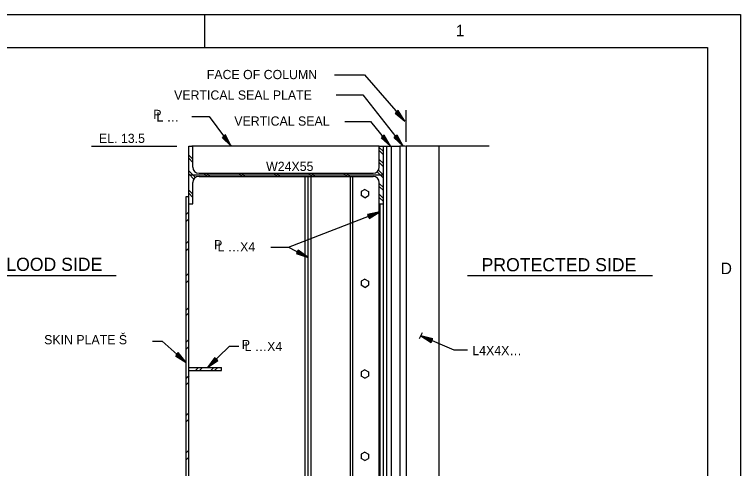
# Model space of a CAD drawing. Extents: x 4.9 to 31.6, y 3.9 to 22.6.
# Drawn here: x 24.23 to 31.57, y 18 to 22.59 of the extents above; entities that cross this region are included whole.
import ezdxf

# ---------------------------------------------------------------- set-up
doc = ezdxf.new("R2010")
doc.units = 0
for name, color, linetype in [('Level 1', 7, 'Continuous'), ('Level 10', 7, 'Continuous'), ('Level 2', 7, 'Continuous'), ('Level 25', 7, 'Continuous'), ('Level 3', 7, 'Continuous'), ('Level 44', 7, 'Continuous'), ('Level 50', 7, 'Continuous')]:
    doc.layers.add(name, color=color, linetype=linetype)

msp = doc.modelspace()

# ---------------------------------------------------------------- linework, layer by layer
at = {"layer": 'Level 1'}
msp.add_line((26.1569, 22.2594), (26.1569, 22.5927), dxfattribs=at)
for points in [[(4.9069, 22.5927), (31.5735, 22.5927), (31.5735, 3.926), (4.9069, 3.926)], [(5.9069, 22.2594), (31.2402, 22.2594), (31.2402, 4.2594), (5.9069, 4.2594)]]:
    msp.add_lwpolyline(points, close=True, dxfattribs=at)
at = {"layer": 'Level 10'}
for p, q in [((26.0618, 18.9926), (26.093, 19.0238)), ((26.1012, 18.9926), (26.1325, 19.0238)), ((26.2154, 18.9926), (26.2467, 19.0238)), ((26.2549, 18.9926), (26.2862, 19.0238))]:
    msp.add_line(p, q, dxfattribs=at)
at = {"layer": 'Level 2'}
for p, q in [((25.9927, 20.6801), (25.9927, 21.2634)), ((25.9927, 21.2634), (26.0343, 21.2634)), ((27.9197, 21.2634), (26.0239, 21.2634)), ((26.0343, 21.0499), (26.0343, 21.2634)), ((26.4504, 21.2634), (26.0773, 21.2634)), ((27.9197, 21.0499), (27.9197, 21.2634)), ((27.9197, 21.2634), (27.9614, 21.2634)), ((27.9614, 21.2634), (28.1281, 21.2634)), ((27.9614, 20.6801), (27.9614, 21.2634)), ((27.9927, 21.2634), (27.9927, 16.5655)), ((28.0395, 21.2634), (28.0395, 15.6699)), ((28.1854, 21.2634), (28.1281, 21.2634)), ((29.0327, 21.2634), (28.1906, 21.2634)), ((25.9927, 20.9717), (27.9614, 20.9717)), ((26.0968, 20.9874), (27.8572, 20.9874)), ((26.0968, 20.9561), (27.8572, 20.9561)), ((27.1697, 17.5238), (27.1697, 20.9561)), ((27.201, 17.5238), (27.201, 20.9561)), ((27.2319, 15.7584), (27.2319, 20.9561)), ((27.6281, 17.1475), (27.6281, 20.9561)), ((26.0343, 20.6801), (26.0343, 20.8936)), ((27.9197, 20.6801), (27.9197, 20.8936)), ((27.7742, 20.8244), (27.7378, 20.8034)), ((27.7378, 20.8034), (27.7378, 20.7616)), ((27.7742, 20.8244), (27.8105, 20.8034)), ((27.8105, 20.8034), (27.8105, 20.7616)), ((25.9666, 20.753), (25.9927, 20.753)), ((25.9666, 17.0688), (25.9666, 20.753)), ((27.7742, 20.7406), (27.7378, 20.7616)), ((27.7742, 20.7406), (27.8105, 20.7616)), ((25.9927, 20.6801), (26.0343, 20.6801)), ((25.9927, 17.0688), (25.9927, 20.6801)), ((27.9197, 20.6801), (27.9614, 20.6801)), ((27.9197, 15.781), (27.9197, 20.6801)), ((27.9302, 17.5238), (27.9302, 20.6801)), ((27.9614, 17.5238), (27.9614, 20.6801)), ((27.7746, 19.9181), (27.7382, 19.8971)), ((27.7746, 19.9181), (27.8109, 19.8971)), ((27.7382, 19.8971), (27.7382, 19.8553)), ((27.7746, 19.8343), (27.7382, 19.8553)), ((27.7746, 19.8343), (27.8109, 19.8553)), ((27.8109, 19.8971), (27.8109, 19.8553)), ((25.9927, 18.9926), (25.9927, 19.0238)), ((26.326, 18.9926), (26.326, 19.0238)), ((27.7746, 19.0014), (27.7382, 18.9804)), ((27.7382, 18.9804), (27.7382, 18.9386)), ((27.7746, 19.0014), (27.8109, 18.9804)), ((27.8109, 18.9804), (27.8109, 18.9386)), ((27.7746, 18.9176), (27.7382, 18.9386)), ((27.7746, 18.9176), (27.8109, 18.9386)), ((27.7746, 18.1685), (27.7382, 18.1475)), ((27.7382, 18.1475), (27.7382, 18.1057)), ((27.7746, 18.1685), (27.8109, 18.1475)), ((27.8109, 18.1475), (27.8109, 18.1057)), ((27.7746, 18.0847), (27.7382, 18.1057)), ((27.7746, 18.0847), (27.8109, 18.1057))]:
    msp.add_line(p, q, dxfattribs=at)
at = {"layer": 'Level 25'}
for p, q in [((28.1906, 21.3056), (28.1906, 21.626)), ((27.9614, 21.2069), (27.9197, 21.2485)), ((26.0343, 21.1295), (25.9927, 21.1712)), ((27.9614, 21.1755), (27.9197, 21.2172)), ((26.0343, 21.0982), (25.9927, 21.1398)), ((27.9614, 21.0852), (27.9197, 21.1268)), ((27.9614, 21.0538), (27.9197, 21.0955)), ((26.0616, 20.9452), (25.9927, 21.0142)), ((27.9614, 20.9389), (27.8988, 21.0014)), ((27.9614, 20.9702), (27.9154, 21.0162)), ((26.0458, 20.9297), (25.9927, 20.9828)), ((26.1764, 20.9561), (26.1451, 20.9874)), ((26.2078, 20.9561), (26.1765, 20.9874)), ((26.5299, 20.9561), (26.4987, 20.9874)), ((26.5613, 20.9561), (26.5301, 20.9874)), ((26.8835, 20.9561), (26.8522, 20.9874)), ((26.9149, 20.9561), (26.8836, 20.9874)), ((27.237, 20.9561), (27.2058, 20.9874)), ((27.2684, 20.9561), (27.2372, 20.9874)), ((27.5906, 20.9561), (27.5594, 20.9874)), ((27.622, 20.9561), (27.5907, 20.9874)), ((27.9614, 20.8438), (27.9197, 20.8854)), ((27.9614, 20.8124), (27.9197, 20.854)), ((26.0343, 20.776), (25.9927, 20.8176)), ((26.0343, 20.7446), (25.9927, 20.7863)), ((27.9614, 20.7338), (27.9197, 20.7755)), ((27.9614, 20.7025), (27.9197, 20.7441)), ((25.2586, 19.952), (23.9288, 19.952)), ((30.6836, 19.952), (28.8131, 19.952)), ((28.3545, 19.375), (28.3242, 19.3143))]:
    msp.add_line(p, q, dxfattribs=at)
for centre, start, end in [((26.0968, 21.0499), 180, 270), ((27.8572, 21.0499), 270, 0), ((26.0968, 20.8936), 90, 180), ((27.8572, 20.8936), 0, 90)]:
    msp.add_arc(centre, 0.0625, start, end, dxfattribs=at)
at = {"layer": 'Level 3'}
for p, q in [((28.156, 21.5419), (28.156, 21.5419)), ((28.1788, 21.5158), (28.1788, 21.5158))]:
    msp.add_line(p, q, dxfattribs=at)
for points in [[(27.4657, 21.9831), (27.7713, 21.9831), (28.1788, 21.5158)], [(27.4852, 21.7803), (27.7533, 21.7803), (28.1612, 21.2634)], [(28.0813, 21.5961), (28.1788, 21.5158), (28.1125, 21.6233), (28.0858, 21.6001), (28.156, 21.5419), (28.111, 21.6149), (28.0939, 21.6), (28.1341, 21.567), (28.1094, 21.6065), (28.1024, 21.6004), (28.1114, 21.5931)], [(27.5707, 21.513), (27.8314, 21.513), (28.0328, 21.2634)], [(28.6776, 19.1997), (28.3397, 19.3454)], [(25.6265, 19.2923), (25.7251, 19.2923), (25.9666, 19.0763)], [(26.4983, 19.2362), (26.4029, 19.2362), (26.1816, 19.0238)]]:
    msp.add_lwpolyline(points, dxfattribs=at)
at = {"layer": 'Level 44'}
for p, q in [((26.0257, 21.5613), (26.2011, 21.5613)), ((26.2011, 21.5613), (26.4235, 21.2634)), ((25.9666, 20.5726), (25.9927, 20.5986)), ((27.0013, 20.2402), (27.9252, 20.5965)), ((25.9666, 20.5007), (25.9927, 20.5268)), ((25.9666, 20.2779), (25.9927, 20.304)), ((25.9666, 20.2061), (25.9927, 20.2321)), ((26.8222, 20.2402), (27.0013, 20.2402)), ((27.0013, 20.2402), (27.201, 20.1364)), ((25.9666, 19.9511), (25.9927, 19.9771)), ((25.9666, 19.88), (25.9927, 19.9061)), ((25.9666, 19.6041), (25.9927, 19.6302)), ((25.9666, 19.5498), (25.9927, 19.5758)), ((25.9666, 19.2823), (25.9927, 19.3083)), ((25.9666, 19.2112), (25.9927, 19.2373)), ((25.9927, 19.0238), (26.326, 19.0238)), ((25.9708, 18.9186), (25.9968, 18.9446)), ((25.9927, 18.9926), (26.326, 18.9926)), ((25.9666, 18.8506), (25.9927, 18.8767)), ((25.9666, 18.5418), (25.9927, 18.5679)), ((25.9666, 18.476), (25.9927, 18.5021)), ((25.9666, 18.1625), (25.9927, 18.1885)), ((25.9666, 18.0906), (25.9927, 18.1167))]:
    msp.add_line(p, q, dxfattribs=at)
at = {"layer": 'Level 50'}
for p, q in [((25.0086, 21.2634), (25.8723, 21.2634)), ((26.4027, 21.2912), (26.4027, 21.2912)), ((26.4235, 21.2634), (26.4235, 21.2634)), ((28.011, 21.2904), (28.011, 21.2904)), ((28.0328, 21.2634), (28.0328, 21.2634)), ((28.1281, 21.2634), (28.1281, 15.4926)), ((28.1397, 21.2906), (28.1397, 21.2906)), ((28.1612, 21.2634), (28.1612, 21.2634)), ((28.1906, 21.2634), (28.1906, 15.4926)), ((28.5239, 21.2634), (28.5239, 16.0933)), ((27.6489, 20.9561), (27.6489, 13.8527)), ((27.8929, 20.5841), (27.8929, 20.5841)), ((27.9252, 20.5965), (27.9252, 20.5965)), ((27.1702, 20.1524), (27.1702, 20.1524)), ((27.201, 20.1364), (27.201, 20.1364)), ((28.3397, 19.3454), (28.3397, 19.3454)), ((28.3716, 19.3317), (28.3716, 19.3317)), ((28.8117, 19.1997), (28.6776, 19.1997)), ((25.9408, 19.0994), (25.9408, 19.0994)), ((25.9666, 19.0763), (25.9666, 19.0763)), ((26.1816, 19.0238), (26.1816, 19.0238)), ((26.2066, 19.0478), (26.2066, 19.0478))]:
    msp.add_line(p, q, dxfattribs=at)
for points in [[(26.3323, 21.3509), (26.4235, 21.2634), (26.3654, 21.3757), (26.3371, 21.3545), (26.4027, 21.2912), (26.3633, 21.3674), (26.3451, 21.3538), (26.3828, 21.3179), (26.3611, 21.3591), (26.3537, 21.3535), (26.362, 21.3457)], [(27.9384, 21.3474), (28.0328, 21.2634), (27.9706, 21.3734), (27.9431, 21.3512), (28.011, 21.2904), (27.9688, 21.3651), (27.9511, 21.3508), (27.9901, 21.3163), (27.9669, 21.3567), (27.9597, 21.3509), (27.9683, 21.3433)], [(28.0677, 21.3485), (28.1612, 21.2634), (28.1002, 21.3741), (28.0724, 21.3522), (28.1397, 21.2906), (28.0982, 21.3658), (28.0804, 21.3517), (28.1191, 21.3168), (28.0963, 21.3574), (28.089, 21.3516), (28.0976, 21.344)], [(27.8163, 20.5324), (27.9252, 20.5965), (27.8014, 20.571), (27.8142, 20.538), (27.8929, 20.5841), (27.8088, 20.5667), (27.817, 20.5455), (27.8618, 20.5721), (27.8162, 20.5624), (27.8196, 20.5536), (27.8294, 20.5596)], [(27.0808, 20.1756), (27.201, 20.1364), (27.0999, 20.2123), (27.0836, 20.1809), (27.1702, 20.1524), (27.1015, 20.2039), (27.0911, 20.1838), (27.1406, 20.1678), (27.1032, 20.1955), (27.0989, 20.1872), (27.1099, 20.1838)], [(28.4624, 19.315), (28.3397, 19.3454), (28.446, 19.2771), (28.46, 19.3095), (28.3716, 19.3317), (28.4438, 19.2853), (28.4527, 19.3061), (28.4022, 19.3185), (28.4415, 19.2935), (28.4452, 19.3021), (28.434, 19.3048)], [(25.8599, 19.144), (25.9666, 19.0763), (25.8875, 19.1748), (25.8639, 19.1485), (25.9408, 19.0994), (25.887, 19.1663), (25.8719, 19.1494), (25.9159, 19.1216), (25.8865, 19.1578), (25.8803, 19.1508), (25.8901, 19.1447)], [(26.2572, 19.1251), (26.1816, 19.0238), (26.2859, 19.0952), (26.2614, 19.1207), (26.2066, 19.0478), (26.2774, 19.0963), (26.2617, 19.1127), (26.2307, 19.0709), (26.2689, 19.0975), (26.2625, 19.1042), (26.2557, 19.0949)]]:
    msp.add_lwpolyline(points, dxfattribs=at)

# ---------------------------------------------------------------- texts
at = {"layer": 'Level 1'}
for s, p in [('1', (28.6941, 22.3719)), ('D', (31.3742, 19.9683))]:
    msp.add_text(s, height=0.1168, dxfattribs=at).set_placement(p)
at = {"layer": 'Level 25'}
for s, height, p in [('FACE OF COLUMN', 0.093292, (26.1756, 21.9396)), ('VERTICAL SEAL PLATE', 0.093292, (25.8451, 21.732)), ('P', 0.0933, (25.6347, 21.536)), ('L …', 0.09329, (25.6661, 21.5113)), ('VERTICAL SEAL', 0.093292, (26.4538, 21.4692)), ('EL. 13.5', 0.09329, (25.0852, 21.2946)), ('W24X55', 0.09329, (26.7756, 21.0109)), ('P', 0.0933, (26.2495, 20.2185)), ('L …X4', 0.09329, (26.284, 20.1974)), ('FLOOD SIDE', 0.13329, (24.039, 20.0009)), ('PROTECTED SIDE', 0.133292, (28.955, 19.9969)), ('SKIN PLATE Š', 0.093292, (24.5304, 19.2592)), ('P', 0.0933, (26.5294, 19.2099)), ('L …X4', 0.09329, (26.5572, 19.19)), ('L4X4X…', 0.09329, (28.8615, 19.1492))]:
    msp.add_text(s, height=height, dxfattribs=at).set_placement(p)

doc.saveas('drawing.dxf')
